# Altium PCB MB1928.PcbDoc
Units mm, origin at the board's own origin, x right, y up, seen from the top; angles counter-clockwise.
Board outline 32.1 x 44.98 mm, 4 copper layers (Top Layer, Layer 1, Layer 2, Bottom Layer), stack 0.76 mm thick; 39 components, 36 nets, 187 pads, 210 vias.
Unrouted connection lines stored in the file: 55.
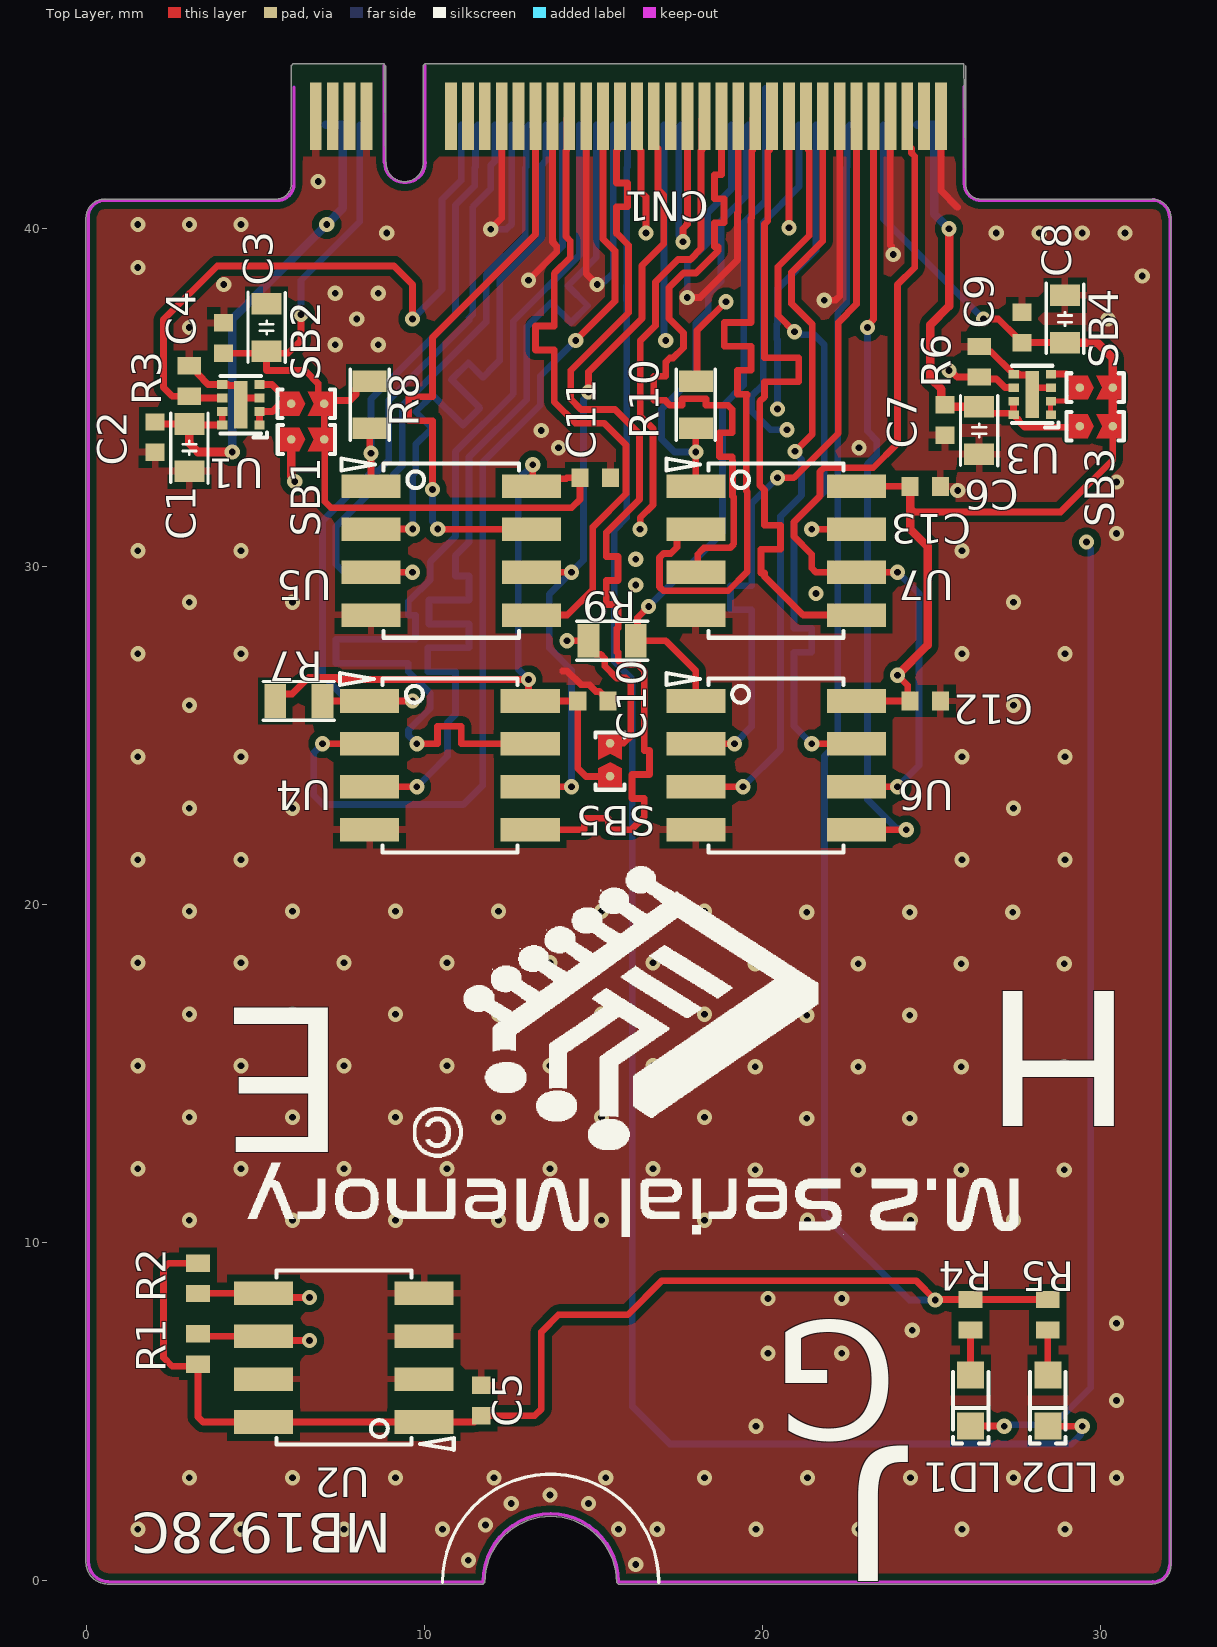
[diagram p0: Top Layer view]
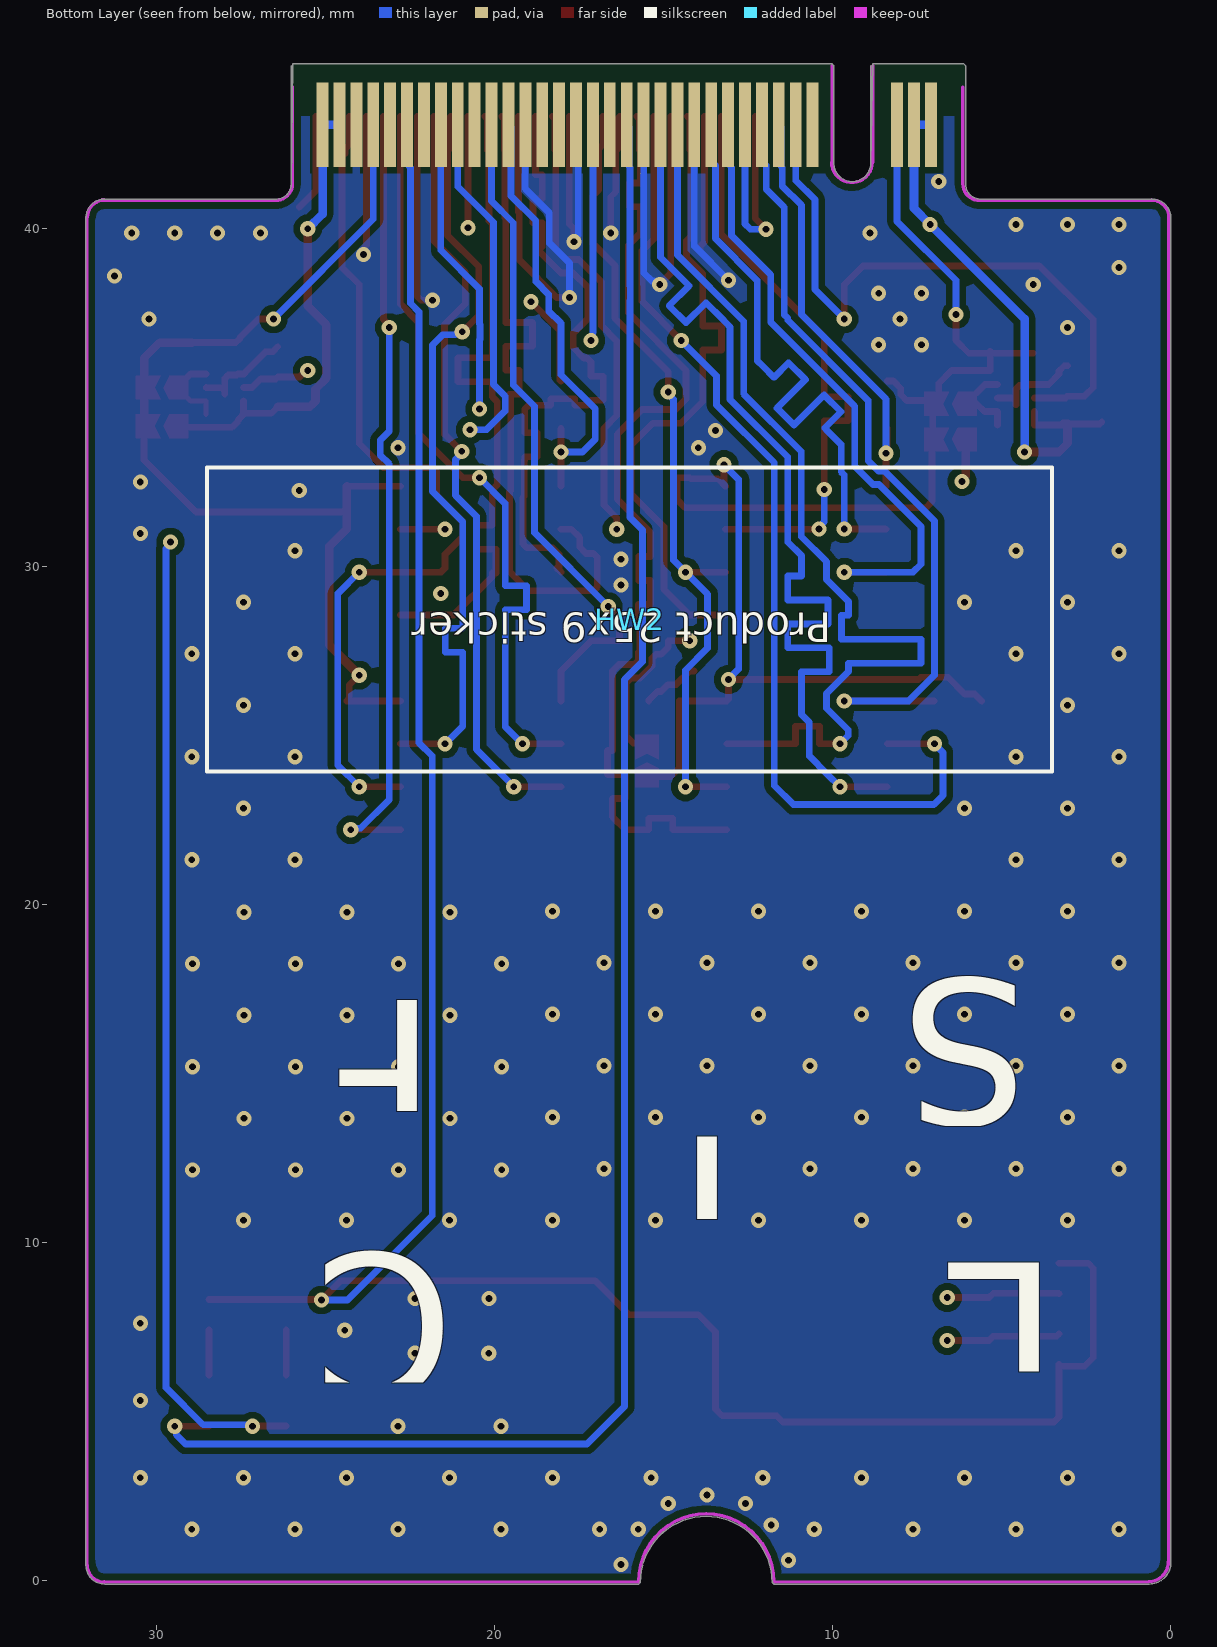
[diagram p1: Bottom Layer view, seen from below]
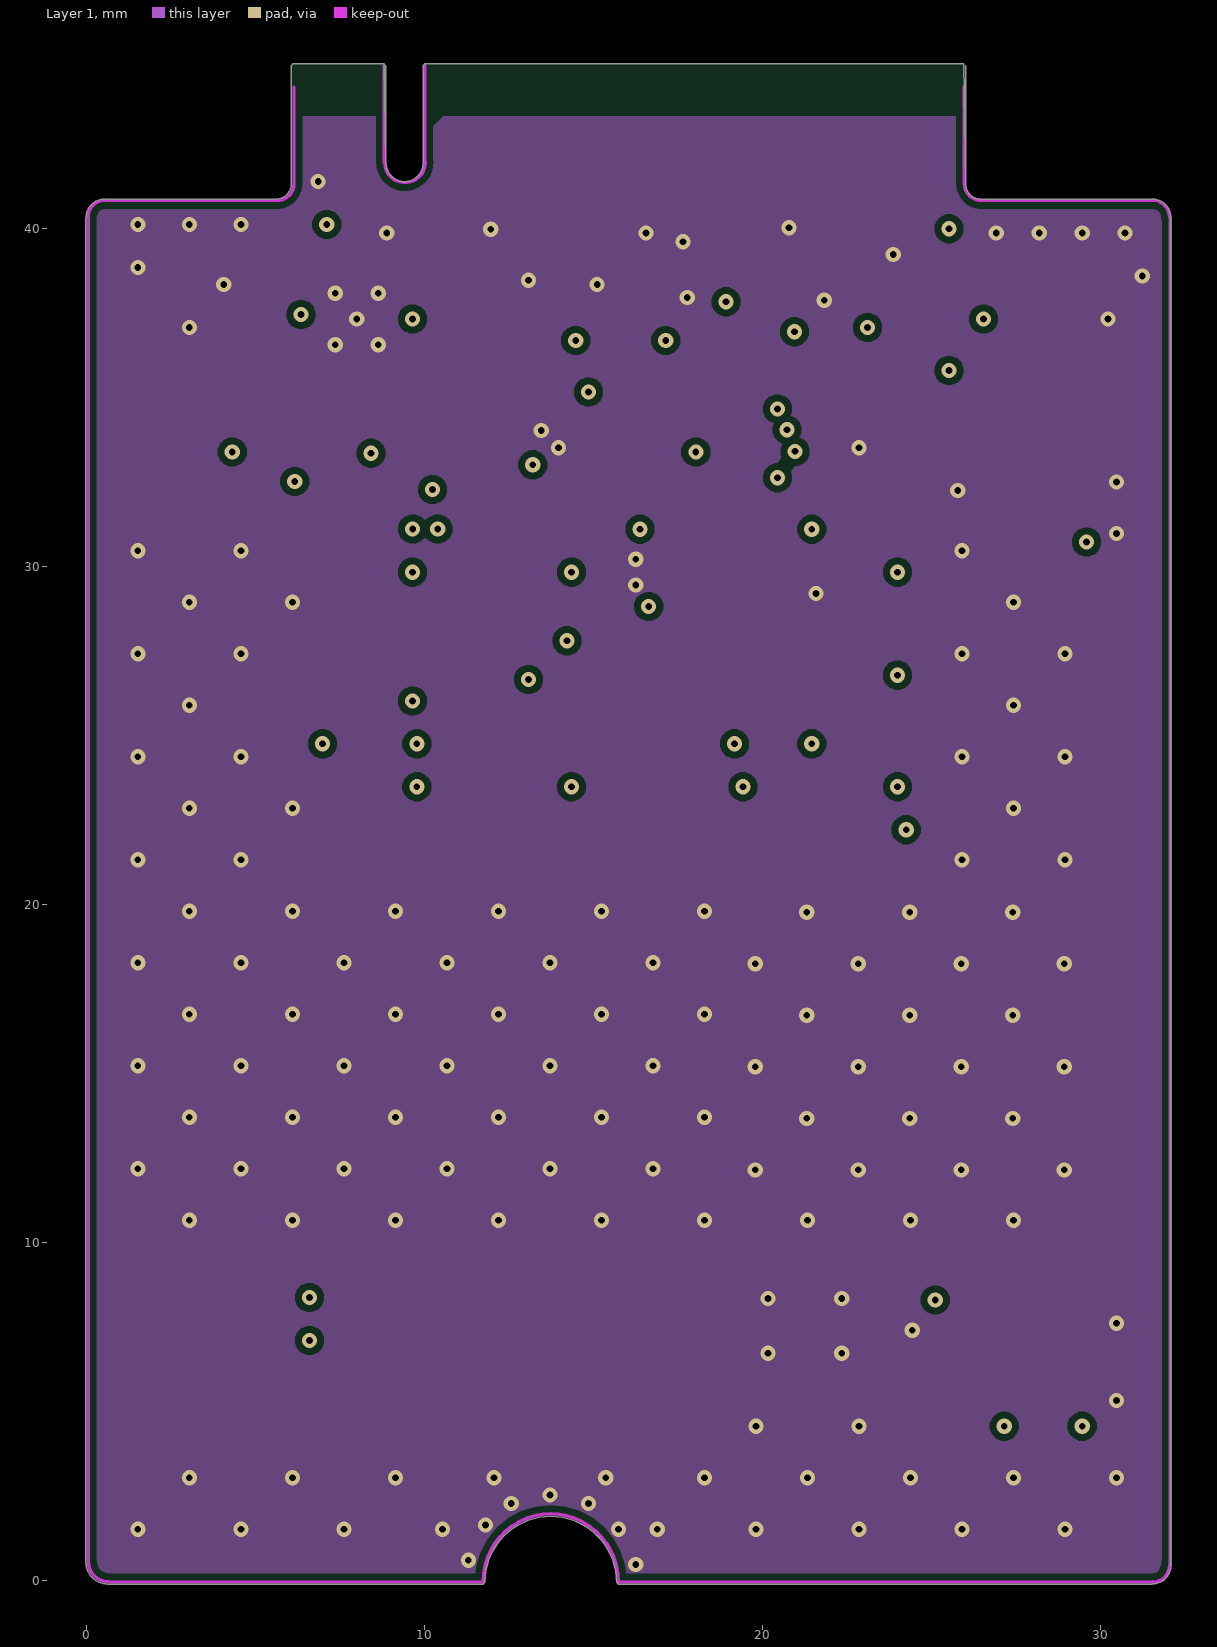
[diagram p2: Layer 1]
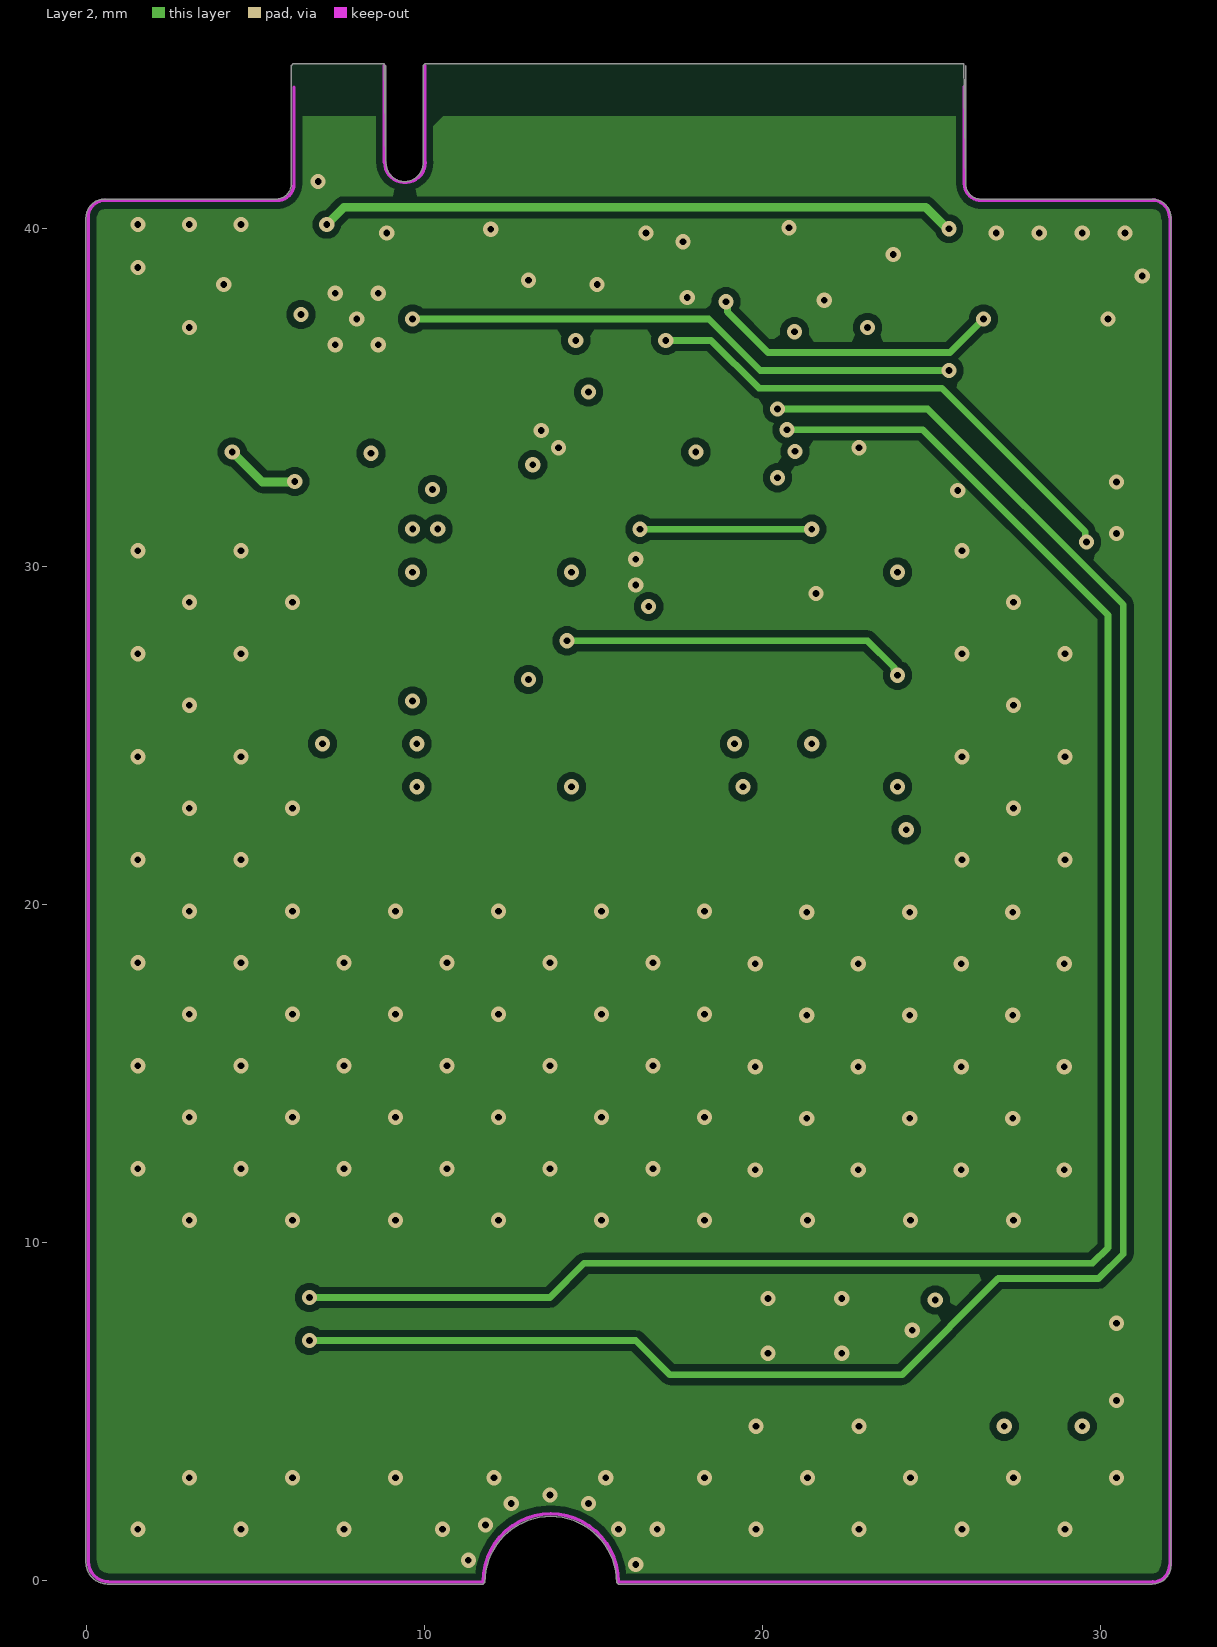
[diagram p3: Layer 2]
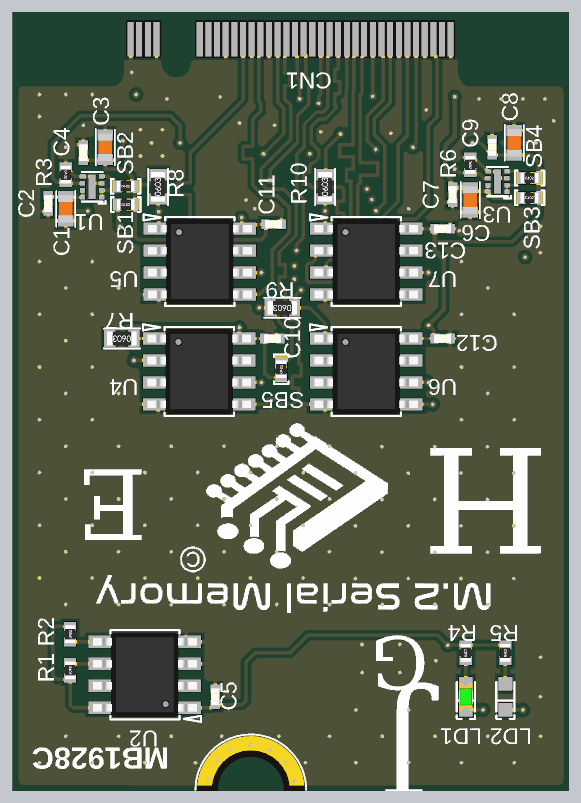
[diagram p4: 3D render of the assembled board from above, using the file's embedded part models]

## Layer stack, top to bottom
Top Solder: solder mask 0.018, Solder Resist, Dk 3.5
Top Layer: signal copper 0.036
Dielectric 2: prepreg 0.109, PP-006, Dk 4.1
Layer 1: signal copper 0.03
Dielectric 1: dielectric 0.41, FR-4, Dk 4.8
Layer 2: signal copper 0.03
Dielectric 3: prepreg 0.109, PP-006, Dk 4.1
Bottom Layer: signal copper 0.036
Bottom Solder: solder mask 0.018, Solder Resist, Dk 3.5

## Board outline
-0.011,0.543 ccw(c0.626,0.543) 0.626,-0.094 11.739,-0.094 11.789,-0.044 cw(c13.739,-0.044) 15.689,-0.044 15.739,-0.094 31.539,-0.094 31.54,-0.094 ccw(c31.539,0.456) 32.089,0.456 32.089,40.331 ccw(c31.539,40.331) 31.539,40.881 26.464,40.881 cw(c26.464,41.331) 26.015,41.331 26.015,44.831 26.015,41.331 25.964,44.881 10.014,44.881 9.964,44.831 9.964,41.951 cw(c9.414,41.951) 9.414,41.401 cw(c9.414,41.951) 8.864,41.951 8.864,44.831 8.864,41.951 8.814,44.881 6.114,44.881 6.064,44.831 6.064,41.331 cw(c5.614,41.331) 5.614,40.881 0.539,40.881 ccw(c0.539,40.331) -0.011,40.331

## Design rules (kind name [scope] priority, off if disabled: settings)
Clearance [All] p1: gap=0.2 ignorepadtopadclearanceinfootprint=TRUE except(0: Arc-Hole Track-Hole SMDPad-Hole THPad-Hole Via-Hole Fill-Hole Poly-Hole Region-Hole Text-Hole; 0.1: Arc-SMDPad Track-SMDPad)
ComponentClearance [All] p1: gap=0.2 collisioncheckmode=3 verticalgap=0.2 showdistances=FALSE
HoleSize [All] p1: absolutevalues=TRUE maxlimit=10 minlimit=0.025 maxpercent=80.000 minpercent=20.000
MatchedLengths MatchedLengths_3 [InNetClass('QSPI1')] p1: tolerance=1 checknetsindiffpair=FALSE checkdiffpairvsdiffpair=TRUE checkxsignals=TRUE checkothers=TRUE
MatchedLengths MatchedLengths_2 [InNetClass('QSPI2')] p2: tolerance=1 checknetsindiffpair=FALSE checkdiffpairvsdiffpair=TRUE checkxsignals=TRUE checkothers=TRUE
MatchedLengths MatchedLengths_1 [InNetClass('QSPI3')] p3: tolerance=1 checknetsindiffpair=FALSE checkdiffpairvsdiffpair=TRUE checkxsignals=TRUE checkothers=TRUE
MatchedLengths [InNetClass('QSPI4')] p4: tolerance=1 checknetsindiffpair=FALSE checkdiffpairvsdiffpair=TRUE checkxsignals=TRUE checkothers=TRUE
MinimumSolderMaskSliver [All] p1: minsoldermaskwidth=0.05
PlaneConnect [All] p1: planeconnectstyle=Relief reliefexpansion=0.508 reliefentries=4 reliefconductorwidth=0.21 reliefairgap=0.21
PolygonConnect PolygonConnect_via [IsVia] p1: connectstyle=Direct reliefconductorwidth=0.254 reliefentries=4 polygonreliefangle="90 Angle" airgapwidth=0.254
PolygonConnect [All] p2: connectstyle=Relief reliefconductorwidth=0.2 reliefentries=4 polygonreliefangle="90 Angle" airgapwidth=0.2
RoutingVias [All] p1: holewidth=0.3 width=0.8 viastyle="Through Hole" minholewidth=0.3 minwidth=0.8 maxholewidth=0.3 maxwidth=0.8
SilkToSilkClearance [All] p1: silktosilkclearance=0.1
SilkToSolderMaskClearance [IsPad] p1: minsilkscreentomaskgap=0.05 clearancetoexposedcopper=TRUE
SolderMaskExpansion [All] p1: expansion=0.102 istentingtop=FALSE
SupplyNets "Schematic Supply Nets_4" [InNet('VDDIO2')] p1: voltage=0.000
SupplyNets "Schematic Supply Nets_3" [InNet('GND')] p2: voltage=0.000
SupplyNets "Schematic Supply Nets_2" [InNet('VDDIO1')] p3: voltage=0.000
SupplyNets "Schematic Supply Nets_1" [InNet('3V3')] p4: voltage=0.000
SupplyNets "Schematic Supply Nets" [InNet('VDDI2C')] p5: voltage=0.000
Width [All] p1: maxlimit=1 minlimit=0.127 preferedwidth=0.254 toplayer_prefwidth=0.2 midlayer1_maxwidth=0.512 midlayer2_maxwidth=0.512 bottomlayer_prefwidth=0.2 minimp=50.000000 maximp=50.000000 favimp=50.000000
24 further rules are at their usual default settings.

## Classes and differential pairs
component class Project_Overview: HW1 HW2
net class QSPI4: QSPI4_D0 QSPI4_D1 QSPI4_D2 QSPI4_D3
net class QSPI3: QSPI3_D0 QSPI3_D1 QSPI3_D2 QSPI3_D3
net class QSPI2: QSPI2_D0 QSPI2_D1 QSPI2_D2 QSPI2_D3
net class QSPI1: QSPI1_D0 QSPI1_D1 QSPI1_D2 QSPI1_D3
component class U_Peripherals: C1 C2 C3 C4 C5 C6 C7 C8 C9 LD1 LD2 R1 R2 R3 R4 R5 R6 SB1 SB2 SB3 SB4 SB5 U1 U2 U3
component class U_M.2_Memory: C10 C11 C12 C13 CN1 R7 R8 R9 R10 U4 U5 U6 U7

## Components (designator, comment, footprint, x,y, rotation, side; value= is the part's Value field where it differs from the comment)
C1 "Capacitor" C0603 3.048,33.528 r90 top value=1uF
C2 "Capacitor" C0402 2.032,33.84 r90 top value=100nF
C3 "Capacitor" C0603 5.334,37.084 r270 top value=1uF
C4 "Capacitor" C0402 4.064,36.772 r270 top value=100nF
C5 "Capacitor" C0402 11.684,5.334 r270 top value=100nF
C6 "Capacitor" C0603 26.416,34.036 r90 top value=1uF
C7 "Capacitor" C0402 25.4,34.348 r90 top value=100nF
C8 "Capacitor" C0603 28.956,37.338 r270 top value=1uF
C9 "Capacitor" C0402 27.686,37.084 r270 top value=100nF
C10 "Capacitor" C0402 14.986,26.035 r180 top value=100nF
C11 "Capacitor" C0402 15.055,32.639 r180 top value=100nF
C12 "Capacitor" C0402 24.823,26.035 r180 top value=100nF
C13 "Capacitor" C0402 24.823,32.385 r180 top value=100nF
CN1 "M2-Generic_Module-KeyA" "M2_Key A" 6.114,44.831 r270 top locked value=M2
HW2 "STICKER_PRODUCT" STICKER_PRODUCT_25X9 16.002,28.448 r0 bottom value=N/A
LD1 "LED_green" LED_0603_OSRAM_LG-Q396-PS-35_GREEN_1A2K_H0P4 26.162,5.334 r270 top value=Green
LD2 "LED_red" LED_0603_VISHAY_VLMS1300-GS08_RED_1A2K_H0P8 28.448,5.334 r270 top value=Red
R1 "Resistor" R0402 3.302,6.858 r270 top value=10K
R2 "Resistor" R0402 3.302,8.948 r90 top value=10K
R3 "Resistor" R0402 3.048,35.502 r270 top value=10K
R4 "Resistor" R0402 26.162,7.874 r90 top value=220R
R5 "Resistor" R0402 28.448,7.874 r90 top value=220R
R6 "Resistor" R0402 26.416,36.068 r270 top value=10K
R7 "Resistor" R0603 6.288,26.035 r180 top value=100K
R8 "Resistor" R0603 8.382,34.798 r90 top value=100K
R9 "Resistor" R0603 15.559,27.813 r180 top value=100K
R10 "Resistor" R0603 18.034,34.798 r90 top value=100K
SB1 "SB_ON" SOLDER-BRIDGE_R0402-0R 6.513,33.773 r0 top value=0R
SB2 "SB_ON" SOLDER-BRIDGE_R0402-0R 6.51,34.829 r0 top value=0R
SB3 "SB_ON" SOLDER-BRIDGE_R0402-0R 29.845,34.163 r0 top value=0R
SB4 "SB_ON" SOLDER-BRIDGE_R0402-0R 29.845,35.306 r0 top value=0R
SB5 "SB_ON" SOLDER-BRIDGE_R0402-0R 15.494,24.257 r90 top value=0R
U1 "IC_LD56100DPUxxR" ICC_DFN8-EPAD_1P6X1P2_P040_H0P45 4.572,34.798 r90 top value=AP7368D-18RS4-7
U2 "M24128-DFMN6TP" ICC_SO8_5X4_P127 7.62,6.604 r90 top
U3 "IC_LD56100DPUxxR" ICC_DFN8-EPAD_1P6X1P2_P040_H0P45 27.991,35.103 r90 top value=AP7368D-18RS4-7
U4 "M95P32" ICC_SO8_5X4_P127 10.757,24.13 r270 top value=M95P32-IXMNT/E
U5 "M95P32" ICC_SO8_5X4_P127 10.795,30.48 r270 top value=M95P32-IXMNT/E
U6 "M95P32" ICC_SO8_5X4_P127 20.409,24.13 r270 top value=M95P32-IXMNT/E
U7 "M95P32" ICC_SO8_5X4_P127 20.409,30.48 r270 top value=M95P32-IXMNT/E

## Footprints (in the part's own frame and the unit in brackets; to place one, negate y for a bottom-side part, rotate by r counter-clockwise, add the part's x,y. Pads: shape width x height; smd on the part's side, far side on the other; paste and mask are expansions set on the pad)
C0402 [mm]
  rect 0.51x0.56 smd mask+0.05: 1(-0.45,0) 2(0.45,0)
  body extent -0.5,-0.3 0.5,0.3, height 0.4
C0603 [mm]
  rect 0.64x0.89 smd mask+0.05: 1(-0.7,0) 2(0.7,0)
  silkscreen extent -1.05,-0.55 1.02,0.55, body extent -0.9,-0.5 0.9,0.5, height 1.4
ICC_DFN8-EPAD_1P6X1P2_P040_H0P45 [mm] "MCD-02937"
  rect 0.26x0.3 smd mask+0.035: 1(-0.6,-0.55) 2(-0.2,-0.55) 3(0.2,-0.55) 4(0.6,-0.55) 5(0.6,0.55) 6(0.2,0.55) 7(-0.2,0.55) 8(-0.6,0.55)
  rect 1.4x0.4 smd mask+0.05: EP(0,0)
  silkscreen extent -0.97,-0.77 0.85,0.6, body extent -0.8,-0.65 0.8,0.65, height 0.51
ICC_SO8_5X4_P127 [mm]
  rect 0.7x1.75 smd mask+0.05: 1(-1.905,-2.375) 2(-0.635,-2.375) 3(0.635,-2.375) 4(1.905,-2.375) 5(1.905,2.375) 6(0.635,2.375) 7(-0.635,2.375) 8(-1.905,2.375)
  silkscreen extent -2.73,-3.25 2.58,2, body extent -2.57,-3 2.57,3, height 1.75
LED_0603_OSRAM_LG-Q396-PS-35_GREEN_1A2K_H0P4 [mm]
  rect 0.8x0.8 smd mask+0.05: 1(-0.75,0) 2(0.75,0)
  silkscreen extent -0.85,-0.53 1.28,0.53, body extent -0.85,-0.45 0.85,0.45, height 0.6
LED_0603_VISHAY_VLMS1300-GS08_RED_1A2K_H0P8 [mm]
  rect 0.8x0.8 smd mask+0.05: 1(-0.75,0) 2(0.75,0)
  silkscreen extent -0.85,-0.53 1.28,0.53, body extent -0.85,-0.45 0.85,0.45, height 0.8
"M2_Key A" [mm] "M2 PCB 0.8mm Key  A"
  rect 2x0.35 smd: 1(1.5,0.675) 3(1.5,1.175) 5(1.5,1.675) 7(1.5,2.175) 17(1.5,4.675) 19(1.5,5.175) 21(1.5,5.675) 23(1.5,6.175) 25(1.5,6.675) 27(1.5,7.175) 29(1.5,7.675) 31(1.5,8.175) 33(1.5,8.675) 35(1.5,9.175) 37(1.5,9.675) 39(1.5,10.175) 41(1.5,10.675) 43(1.5,11.175) 45(1.5,11.675) 47(1.5,12.175) 49(1.5,12.675) 51(1.5,13.175) 53(1.5,13.675) 55(1.5,14.175) 57(1.5,14.675) 59(1.5,15.175) 61(1.5,15.675) 63(1.5,16.175) 65(1.5,16.675) 67(1.5,17.175) 69(1.5,17.675) 71(1.5,18.175) 73(1.5,18.675) 75(1.5,19.175)
  rect 2.5x0.35 smd far side: 2(1.75,0.975) 4(1.75,1.475) 6(1.75,1.975) 16(1.75,4.475) 18(1.75,4.975) 20(1.75,5.475) 22(1.75,5.975) 24(1.75,6.475) 26(1.75,6.975) 28(1.75,7.475) 30(1.75,7.975) 32(1.75,8.475) 34(1.75,8.975) 36(1.75,9.475) 38(1.75,9.975) 40(1.75,10.475) 42(1.75,10.975) 44(1.75,11.475) 46(1.75,11.975) 48(1.75,12.475) 50(1.75,12.975) 52(1.75,13.475) 54(1.75,13.975) 56(1.75,14.475) 58(1.75,14.975) 60(1.75,15.475) 62(1.75,15.975) 64(1.75,16.475) 66(1.75,16.975) 68(1.75,17.475) 70(1.75,17.975) 72(1.75,18.475) 74(1.75,18.975)
R0402 [mm]
  rect 0.51x0.7 smd mask+0.05: 1(-0.45,0) 2(0.45,0)
  body extent -0.52,-0.3 0.52,0.3, height 0.4
R0603 [mm]
  rect 0.64x1 smd mask+0.05: 1(-0.7,0) 2(0.7,0)
  silkscreen extent -1.05,-0.58 1.05,0.58, body extent -0.9,-0.5 0.9,0.5, height 0.56
SOLDER-BRIDGE_R0402-0R [mil] "MCD-01619"
  round 10 smd paste-393.7: 1(-17.72,0) 2(20.67,0)
  Top Layer region: 1.48,13.78 8.37,0 1.48,-13.78 30.51,-13.78 30.51,13.78
  Top Layer region: -30.51,-13.78 -30.51,13.78 -8.37,13.78 -1.48,0 -8.37,-13.78
  silkscreen extent -33,-17 33,17, body extent -20,-12 20,12, height 14
STICKER_PRODUCT_25X9 [mm] "Sticker to mention board CPN code"
  silkscreen extent -12.5,-4.5 12.5,4.5

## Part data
C1 C3 C6 C8: library part MCD-01100, "Capacitor, MLCC, 1uF, 25V, X5R, +/-10%, 0603, T=0.8mm", Manufacturer=YAGEO, Manufacturer_Part_Number=CC0603KRX5R8BB105, Package=0603
C2 C4 C5 C7 C9 C10 C11 C12 C13: library part MCD-00006, "Capacitor, MLCC, 100nF, 16V, X7R, +/-10%, 0402, T=0.5mm", Manufacturer=YAGEO, Manufacturer_Part_Number=CC0402KRX7R7BB104, Package=0402
CN1: library part MCD-04116, "M2 Male connector, for Micromod, board edge connector 75-pin KEY A", Manufacturer=STMICROELECTRONICS, Manufacturer_Part_Number=N/A
HW2: library part MCD-00547, "Sticker product, 25x9mm", Manufacturer=N/A, Manufacturer_HQ_COO=Unknown
LD1: library part MCD-02901, "LED, Green, 2V, 20mA, 0603", Manufacturer=EVERLIGHT, Manufacturer_Part_Number=19-217/G7C-AN1P2/6T, Package=0603
LD2: library part MCD-02787, "LED, Red, 1V7 to 2V2, 5mA, 0603", Manufacturer=EVERLIGHT, Manufacturer_Part_Number=19-217/R6C-AL1M2VY/6T, Package=0603
R1 R2 R3 R6: library part MCD-00053, "Resistor, 10K, 0402, +/-1%, 1/16W", Manufacturer=YAGEO, Manufacturer_Part_Number=RC0402FR-0710KL, Package=0402
R4 R5: library part MCD-00427, "Resistor, 220R, 0402, +/-1%, 1/16W", Manufacturer=YAGEO, Manufacturer_Part_Number=RC0402FR-07220RL, Package=0402
R7 R8 R9 R10: library part MCD-00223, "Resistor, 100K, 0603, +/- 1%, 1/10W", Manufacturer=YAGEO, Manufacturer_Part_Number=RC0603FR-07100KL, Package=0603
SB1 SB2 SB3 SB4 SB5: library part MCD-01618, "Resistor, 0R, SB0402, 5%, 0.063W", Manufacturer=YAGEO, Manufacturer_Part_Number=RC0402JR-070RL, Package=0402
U1 U3: library part MCD-04735, "LDO, 1A, 1V8, Fast transient, low noise, 16uV RMS Noise, -40 To 85 degree C", Manufacturer="DIODES INCORPORATED", Manufacturer_Part_Number=AP7368D-18RS4-7, Package=DFN8
U2: library part MCD-00293, "Memory, EEPROM, 1V7 to 5V5, 128Kbit, 1MHz, SO-8", Manufacturer=STMICROELECTRONICS, Manufacturer_HQ_COO=EU, Package=SO-8
U4 U5 U6 U7: library part MCD-03804, "Memory, EEPROM, 1.6V to 3.6V, 32Mbit, 80MHz, SO8N, SPI interface", Manufacturer=STMICROELECTRONICS, Manufacturer_Part_Number=M95P32-IXMNT/E, Package=SO8N

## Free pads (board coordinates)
  round 0.508 on Mech16: 1(20.669,-22.395) 1(69.517,-22.395)

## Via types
v1: diameter 0.45, hole 0.2, Top Layer to Bottom Layer, tented both sides, 210 vias

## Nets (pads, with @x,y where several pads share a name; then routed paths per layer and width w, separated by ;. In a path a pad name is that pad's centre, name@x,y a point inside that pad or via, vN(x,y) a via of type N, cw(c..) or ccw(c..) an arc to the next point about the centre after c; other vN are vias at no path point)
3V3: C1.2 C2.2 C6.2 C7.2 CN1.2 CN1.4 CN1.72 CN1.74 SB1.1 SB3.1 U1.7 U1.8 U3.7 U3.8 | length 52
  Top Layer w0.2: C2.2 2.094,34.228 C1.2 ; C1.2@3.173,34.228 3.203,34.198 U1.8 U1.7 ; C6.2 26.608,34.544 U3.8@27.294,34.544 ; U3.7@27.432,34.906 27.432,34.506 27.452,34.506 27.482,34.476 27.482,34.456 27.582,34.356 27.582,34.323 27.774,34.131 29.348,34.131 29.38,34.163 SB3.1
  Top Layer w0.254: C1.2@3.173,34.228 C1.2 3.048,33.655 3.302,33.401 v1(4.318,33.401) ; SB1.1 6.063,32.682 6.166,32.58 v1(6.166,32.527) ; C7.2 25.298,34.9 25.298,35.262 24.975,35.585 24.975,37.167 25.527,37.719 v1(25.527,40.005) ; C7.2@25.462,34.736 C6.2
  Layer 2 w0.2: v1@25.474,40.005 v1(25.527,40.005)
  Layer 2 w0.254: v1(4.318,33.401) 5.207,32.512 v1@5.969,32.512 ; v1(7.112,40.132) 7.62,40.64 24.839,40.64 v1@25.474,40.005
  Bottom Layer w0.254: v1(4.318,33.401) 4.318,37.338 v1(7.112,40.132) 7.589,40.609 CN1.4 CN1.2 ; CN1.72 CN1.74 25.089,40.443 v1(25.527,40.005)
GND: C1.1 C2.1 C3.1 C4.1 C5.1 C6.1 C7.1 C8.1 C9.1 C10.1 C11.1 C12.1 C13.1 CN1.1 CN1.7 CN1.23 CN1.24 CN1.29 CN1.30 CN1.33 CN1.36 CN1.39 CN1.44 CN1.45 CN1.50 CN1.51 CN1.57 CN1.63 CN1.69 CN1.70 CN1.75 R3.1 R6.1 U1.3 U1.5 U1.EP U2.2 U2.3 U2.4 U2.7 U3.3 U3.5 U3.EP U4.4 U5.4 U6.4 U7.4 | length 74
  Top Layer w0.2: R3.1 3.143,35.952 3.298,35.797 3.298,35.702 3.602,35.398 U1.5 4.188,35.398 4.218,35.368 4.472,35.368 4.572,35.268 U1.EP@4.572,34.898 ; U1.EP U1.EP@4.572,34.898 ; U1.3 4.672,34.998 U1.EP@4.572,34.898 ; v1(11.967,39.994) 12.289,40.316 CN1.23 ; v1(13.081,38.481) 13.918,39.318 13.918,39.484 13.789,39.612 CN1.29 ; 14.097,26.924 14.224,26.924 14.633,26.515 14.874,26.515 15.074,26.315 15.181,26.315 15.436,26.06 C10.1 ; CN1.33 14.789,38.678 v1(15.113,38.354) ; CN1.39 16.364,43.256 16.364,42.364 16.414,42.314 16.414,41.099 16.561,40.952 v1(16.561,39.878) ; v1(17.653,39.624) 17.653,40.005 17.789,40.141 CN1.45 ; v1(17.78,37.973) 18.161,37.973 19.266,39.078 19.266,40.475 19.289,40.498 CN1.51 ; v1(20.789,40.036) CN1.57 ; v1(21.833,37.889) 21.837,37.892 22.172,37.892 22.289,38.01 CN1.63 ; CN1.69 23.789,39.517 23.828,39.478 23.828,39.291 v1(23.876,39.243) ; CN1.75 25.289,41.132 25.781,40.64 ; R6.1 26.571,36.363 26.775,36.363 27.382,35.756 27.382,35.736 27.412,35.706 27.432,35.706 27.598,35.706 27.628,35.676 27.882,35.676 27.982,35.576 U3.EP@27.982,35.205 ; U3.EP@27.982,35.106 U3.EP@27.982,35.205 ; U3.3@28.532,35.306 28.531,35.305 28.082,35.305 U3.EP@27.982,35.205
  Bottom Layer w0.2: v1(11.967,39.994) 12.435,39.994 12.589,40.148 CN1.24 ; v1(13.081,38.481) 14.089,39.489 CN1.30 ; v1(15.113,38.354) 15.181,38.354 15.288,38.462 15.348,38.462 15.589,38.703 CN1.36 ; CN1.44 17.526,43.018 17.526,39.819 17.653,39.692 v1(17.653,39.624) ; v1(17.78,37.973) 17.78,38.989 18.379,39.588 18.379,40.477 19.089,41.187 CN1.50
  other v1: 16.256,0.481 11.303,0.608 1.524,1.524 4.572,1.524 7.62,1.524 10.541,1.524 15.748,1.524 16.891,1.524 19.812,1.524 22.86,1.524 25.908,1.524 28.956,1.524 11.811,1.651 12.573,2.286 14.859,2.286 13.716,2.54 3.048,3.048 6.096,3.048 9.144,3.048 12.065,3.048 15.367,3.048 18.288,3.048 21.336,3.048 24.384,3.048 27.432,3.048 30.48,3.048 19.812,4.572 22.86,4.572 30.48,5.334 20.172,6.731 22.352,6.731 24.435,7.417 30.48,7.62 20.168,8.357 22.352,8.357 3.048,10.668 6.096,10.668 9.144,10.668 12.192,10.668 15.24,10.668 18.288,10.668 21.336,10.668 24.384,10.668 27.432,10.668 19.791,12.16 22.839,12.16 25.887,12.16 28.935,12.16 1.524,12.192 4.572,12.192 7.62,12.192 10.668,12.192 13.716,12.192 16.764,12.192 21.315,13.684 24.363,13.684 27.411,13.684 3.048,13.716 6.096,13.716 9.144,13.716 12.192,13.716 15.24,13.716 18.288,13.716 19.791,15.208 22.839,15.208 25.887,15.208 28.935,15.208 1.524,15.24 4.572,15.24 7.62,15.24 10.668,15.24 13.716,15.24 16.764,15.24 21.315,16.732 24.363,16.732 27.411,16.732 3.048,16.764 6.096,16.764 9.144,16.764 12.192,16.764 15.24,16.764 18.288,16.764 19.791,18.256 22.839,18.256 25.887,18.256 28.935,18.256 1.524,18.288 4.572,18.288 7.62,18.288 10.668,18.288 13.716,18.288 16.764,18.288 21.315,19.78 24.363,19.78 27.411,19.78 3.048,19.812 6.096,19.812 9.144,19.812 12.192,19.812 15.24,19.812 18.288,19.812 1.524,21.336 4.572,21.336 25.908,21.336 28.956,21.336 3.048,22.86 6.096,22.86 27.432,22.86 1.524,24.384 4.572,24.384 25.908,24.384 28.956,24.384 3.048,25.908 27.432,25.908 1.524,27.432 4.572,27.432 25.908,27.432 28.956,27.432 3.048,28.956 6.096,28.956 27.432,28.956 21.59,29.21 16.256,29.464 16.256,30.226 1.524,30.48 4.572,30.48 25.908,30.48 30.48,30.988 25.781,32.258 30.48,32.512 13.97,33.528 22.86,33.528 13.462,34.036 7.366,36.576 8.636,36.576 3.048,37.084 8.001,37.338 30.226,37.338 7.366,38.1 8.636,38.1 4.064,38.354 31.242,38.608 1.524,38.862 8.89,39.878 26.924,39.878 28.194,39.878 29.464,39.878 30.734,39.878 1.524,40.132 3.048,40.132 4.572,40.132 6.858,41.402
LDO_EN: CN1.18 R3.2 R6.2 U1.6 U3.6 | length 38.1
  Top Layer w0.2: U1.6 3.102,34.998 R3.2 2.54,35.052 2.286,35.306 2.286,37.318 3.874,38.906 9.1,38.906 9.652,38.354 v1(9.652,37.338) ; v1(25.527,35.814) 25.57,35.814 25.766,35.618 R6.2 26.474,35.56 26.924,35.56 27.178,35.306 U3.6@27.432,35.306
  Layer 2 w0.2: v1(9.652,37.338) 18.415,37.338 19.939,35.814 v1(25.527,35.814)
  Bottom Layer w0.2: v1(9.652,37.338) 10.522,38.208 10.522,40.868 11.089,41.435 CN1.18
LED1: CN1.42 LD1.2 | length 50.6
  Top Layer w0.2: LD1.2 27.148,4.584 v1(27.16,4.572)
  Layer 2 w0.2: v1(17.145,36.703) 18.484,36.703 19.898,35.289 25.31,35.289 29.557,31.042 29.557,30.768 v1(29.591,30.734)
  Bottom Layer w0.2: CN1.42 17.089,36.936 17.097,36.928 17.097,36.751 v1(17.145,36.703) ; v1(27.16,4.572) 27.208,4.619 28.622,4.619 29.718,5.715 29.718,30.539 29.591,30.666 v1(29.591,30.734)
LED2: CN1.38 LD2.2 | length 53.5
  Top Layer w0.2: LD2.2 28.46,4.572 v1(29.464,4.572)
  Bottom Layer w0.2: CN1.38 16.014,43.006 16.014,41.839 15.989,41.814 15.989,38.322 15.985,38.317 15.985,37.883 15.989,37.878 15.989,31.464 15.621,31.095 15.621,27.198 16.154,26.664 16.154,5.156 17.264,4.047 29.144,4.047 29.416,4.319 29.416,4.524 v1(29.464,4.572)
NetLD1_1: LD1.1 R4.1 | length 1.3
  Top Layer w0.2: LD1.1 R4.1
NetLD2_1: LD2.1 R5.1 | length 1.3
  Top Layer w0.2: LD2.1 R5.1
NetSB2_1: SB2.1 U1.1 U1.2 U1.4 | length 2.9
  Top Layer w0.2: U1.1 U1.2 5.504,34.598 5.735,34.829 SB2.1 5.49,35.398 U1.4 ; 5.883,34.619 5.883,34.925
NetSB4_1: SB4.1 U3.1 U3.2 U3.4 | length 2.5
  Top Layer w0.15: U3.1@28.532,34.506 28.532,34.906 28.995,34.906 SB4.1
  Top Layer w0.2: U3.4@28.532,35.706 28.995,35.706 SB4.1
QSPI1/2_CLK: CN1.41 U4.6 U5.6 | length 24
  Top Layer w0.2: U4.6 v1(14.351,23.495) ; U5.6 v1(14.351,29.845) ; v1(14.859,35.179) 14.859,35.771 16.438,37.35 16.438,38.917 17.086,39.565 17.086,40.993 16.914,41.164 16.914,42.381 16.789,42.506 CN1.41
  Bottom Layer w0.2: v1(14.351,23.495) 14.351,26.944 13.699,27.596 13.699,29.193 v1(14.351,29.845) 14.707,30.201 14.707,34.959 14.859,35.111 v1(14.859,35.179)
QSPI1_D0: CN1.37 U4.5 | length 31.1
  Top Layer w0.2: U4.5 14.63,22.225 14.731,22.225 14.731,22.565 15.439,22.565 15.439,22.225 16.129,22.225 16.51,22.606 16.51,23.049 16.51,23.149 16.144,23.149 16.144,23.857 16.662,23.857 16.662,24.565 16.51,24.565 16.51,25.527 16.51,26.289 16.51,26.924 16.321,27.113 15.856,27.113 15.739,27.23 15.739,27.375 15.739,27.475 15.697,27.475 15.697,28.183 15.739,28.183 15.739,28.891 15.386,28.891 15.386,29.599 15.731,29.599 15.731,30.307 15.386,30.307 15.386,31.02 16.364,31.998 16.364,33.928 15.638,34.654 14.642,34.654 14.332,34.964 14.332,35.815 16.038,37.521 16.038,39.519 15.711,39.846 15.689,39.867 15.689,39.946 15.689,40.654 16.014,40.654 16.014,41.362 15.689,41.362 15.689,42.037 15.689,42.314 15.714,42.339 15.714,43.256 CN1.37
QSPI1_D1: CN1.35 U4.2 | length 29.9
  Top Layer w0.2: v1(6.985,24.765) U4.2 ; v1(14.478,36.703) 15.638,37.863 15.638,39.353 15.289,39.702 CN1.35
  Bottom Layer w0.2: v1(6.985,24.765) 6.731,24.511 6.731,23.241 7.002,22.97 11.159,22.97 11.725,23.536 11.725,33.084 13.43,34.789 13.43,35.655 v1(14.478,36.703)
QSPI1_D2: CN1.34 U4.3 | length 29.7
  Top Layer w0.2: U4.3 v1(9.779,23.495)
  Bottom Layer w0.2: v1(9.779,23.495) 10.16,23.876 10.687,24.403 10.687,25.4 10.922,25.635 10.922,26.797 10.922,26.897 10.098,26.897 10.098,27.605 11.325,27.605 11.325,28.313 10.136,28.313 10.136,29.021 11.325,29.021 11.325,29.729 10.922,29.729 10.922,30.099 10.922,30.335 11.325,30.738 11.325,33.25 13.03,34.955 13.03,37.102 13.173,37.246 13.244,37.316 13.745,37.817 14.334,37.228 14.834,37.729 14.245,38.318 14.38,38.452 15.089,39.162 CN1.34
QSPI1_D3: CN1.32 U4.7 | length 30.2
  Top Layer w0.2: v1(9.779,24.765) 10.287,24.765 10.387,24.765 10.387,25.287 11.095,25.287 11.095,24.765 11.938,24.765 U4.7
  Bottom Layer w0.2: v1(9.779,24.765) 9.535,25.009 9.535,25.175 10.177,25.818 10.177,26.252 9.525,26.904 9.525,27.051 9.525,27.151 7.385,27.151 7.385,27.859 9.736,27.859 9.736,28.567 9.525,28.567 9.525,28.829 9.525,28.976 10.177,29.628 10.177,30.156 10.925,30.904 10.925,33.416 12.63,35.121 12.63,37.268 14.589,39.227 CN1.32
QSPI1_NCS: CN1.22 R7.1 U4.1 | length 24.1
  Top Layer w0.2: R7.1 U4.1 v1(9.652,26.035)
  Bottom Layer w0.2: v1(9.652,26.035) 7.747,26.035 6.985,26.797 6.985,31.362 8.461,32.838 8.637,32.838 8.945,33.146 8.945,34.922 11.322,37.299 11.322,37.357 11.43,37.465 11.43,40.645 11.964,41.179 11.964,41.814 11.964,41.881 12.089,42.006 CN1.22
QSPI2_D0: CN1.31 U5.5 | length 19.3
  Top Layer w0.2: U5.5 13.174,28.579 14.228,28.579 14.986,29.337 14.986,31.186 15.964,32.164 15.964,33.604 15.314,34.254 14.476,34.254 13.843,34.887 13.843,36.322 13.843,36.422 13.288,36.422 13.288,37.13 13.843,37.13 13.843,38.481 13.843,38.677 14.318,39.152 14.318,39.649 14.189,39.778 14.189,42.314 14.214,42.339 14.214,43.256 CN1.31
QSPI2_D1: CN1.28 U5.2 | length 18.6
  Top Layer w0.2: U5.2 8.431,31.126 v1(9.654,31.126)
  Bottom Layer w0.2: v1(9.654,31.126) 9.654,32.723 9.745,32.814 9.745,33.621 10.16,34.036 10.231,34.107 9.746,34.592 10.246,35.092 11.141,34.198 11.642,34.698 10.8,35.54 11.301,36.04 11.733,35.609 12.065,35.941 12.23,36.106 12.23,38.481 13.464,39.715 13.464,41.814 13.464,41.881 13.589,42.006 CN1.28
QSPI2_D2: CN1.26 U5.3 | length 19.1
  Top Layer w0.2: U5.3 v1(9.652,29.845)
  Bottom Layer w0.2: v1(9.652,29.845) 7.62,29.845 7.385,30.08 7.385,31.197 8.626,32.438 8.803,32.438 9.345,32.98 9.345,34.757 11.83,37.242 11.83,38.647 12.989,39.806 12.989,41.814 13.014,41.839 13.014,43.006 CN1.26
QSPI2_D3: CN1.27 U5.7 | length 17.7
  Top Layer w0.2: v1(10.243,32.294) 10.243,34.228 10.243,34.328 9.54,34.328 9.54,35.036 10.243,35.036 10.243,36.195 10.243,36.786 13.289,39.832 CN1.27 ; v1@10.406,31.115 U5.7
  Bottom Layer w0.2: v1(10.243,32.294) 10.243,31.346 10.4,31.189 v1(10.4,31.121)
QSPI2_NCS: CN1.20 R8.1 U5.1 | length 12.8
  Top Layer w0.2: R8.1 8.382,33.401 v1(8.42,33.363) U5.1
  Bottom Layer w0.2: v1(8.42,33.363) 8.42,34.963 10.922,37.465 10.922,40.702 11.489,41.269 11.489,41.814 11.514,41.839 11.514,43.006 CN1.20
QSPI3/4_CLK: CN1.71 U6.6 U7.6 | length 26.7
  Top Layer w0.2: U6.6 v1(24.003,23.495) ; v1(24.003,29.845) U7.6 21.58,29.845 21.463,29.962 21.463,30.373 20.938,30.898 20.938,31.332 21.709,32.103 21.709,32.818 21.826,32.935 23.283,32.935 24.003,33.655 24.003,38.354 24.511,38.862 24.511,42.151 24.414,42.248 24.414,42.381 24.289,42.506 CN1.71
  Bottom Layer w0.2: v1(24.003,23.495) 24.638,24.13 24.638,29.21 v1(24.003,29.845)
QSPI3_D0: CN1.67 U6.5 | length 23.5
  Top Layer w0.2: U6.5 v1(24.257,22.225) ; v1(23.114,37.084) 23.114,37.151 23.289,37.326 CN1.67
  Bottom Layer w0.2: v1(23.114,37.084) 23.114,34.016 23.385,33.745 23.385,33.311 23.114,33.04 23.114,23.114 23.959,22.269 24.213,22.269 v1(24.257,22.225)
QSPI3_D1: CN1.65 U6.2 | length 22.7
  Top Layer w0.2: U6.2 v1(19.177,24.765) ; v1(20.447,32.639) 20.934,32.639 22.25,33.955 22.25,37.236 22.789,37.775 CN1.65
  Bottom Layer w0.2: v1(19.177,24.765) 19.685,25.273 19.685,28.636 19.685,28.736 19.059,28.736 19.059,29.444 19.685,29.444 19.685,30.607 19.685,31.877 v1(20.447,32.639)
QSPI3_D2: CN1.61 U6.3 | length 22.9
  Top Layer w0.2: U6.3 v1(19.431,23.495) ; v1(20.971,33.419) 21.48,33.928 21.48,37.174 20.866,37.788 20.866,38.715 21.789,39.639 CN1.61
  Bottom Layer w0.2: v1(19.431,23.495) 20.538,24.602 20.538,31.498 21.158,32.118 21.158,33.177 20.971,33.364 v1(20.971,33.419)
QSPI3_D3: CN1.59 U6.7 | length 22.8
  Top Layer w0.2: v1(20.955,36.957) 20.466,37.446 20.466,38.881 21.389,39.804 21.389,42.314 21.364,42.339 21.364,43.256 CN1.59 ; v1(21.463,24.765) U6.7
  Bottom Layer w0.2: v1(20.955,36.957) 21.003,36.909 21.13,36.909 21.167,36.872 21.528,36.872 21.836,36.565 21.836,32.23 20.938,31.332 20.938,30.988 20.938,28.186 21.46,28.186 21.46,27.478 20.938,27.478 20.938,26.67 20.938,25.29 v1(21.463,24.765)
QSPI3_NCS: CN1.54 R9.1 U6.1 | length 21
  Top Layer w0.2: v1(16.637,28.829) 16.304,28.496 16.304,27.858 R9.1 17.145,27.813 18.034,26.924 U6.1
  Bottom Layer w0.2: v1(16.637,28.829) 18.821,31.013 18.821,34.754 19.448,35.381 19.448,40.182 20.089,40.824 CN1.54 CN1.54@20.089,44.156
QSPI4_D0: CN1.55 U7.5 | length 20.2
  Top Layer w0.2: CN1.55 20.214,43.256 20.214,42.339 20.164,42.289 20.164,40.242 20.066,40.144 20.066,36.703 20.066,36.187 21.08,36.187 21.08,35.479 20.066,35.479 20.066,35.032 19.922,34.888 19.922,34.671 19.922,32.422 20.066,32.278 20.066,31.623 20.066,31.234 20.538,31.234 20.538,30.526 19.958,30.526 19.958,29.818 20.066,29.818 20.066,29.718 21.209,28.575 U7.5
QSPI4_D1: CN1.53 U7.2 | length 21.2
  Top Layer w0.2: U7.2 17.728,31.115 17.478,30.865 17.478,30.582 17.291,30.395 17.076,30.395 16.959,30.278 16.959,29.412 17.076,29.295 18.992,29.295 19.558,29.861 19.558,32.22 19.522,32.256 19.522,34.478 19.522,35.054 19.558,35.09 19.558,35.11 19.268,35.11 19.268,35.818 19.666,35.818 19.666,36.526 18.877,36.526 18.877,37.234 19.666,37.234 19.666,38.042 19.666,40.309 19.689,40.333 19.689,42.314 19.714,42.339 19.714,43.256 CN1.53
QSPI4_D2: CN1.49 U7.3 | length 20.3
  Top Layer w0.2: 18.091,30.378 18.091,29.902 U7.3 U7.3@18.161,29.972 ; 18.161,30.448 18.278,30.565 19.041,30.565 19.158,30.682 19.158,32.054 19.122,32.09 19.122,33.147 19.109,33.16 19.109,33.26 18.734,33.26 18.734,33.968 19.109,33.968 19.109,34.417 19.109,34.665 18.992,34.782 18.956,34.782 18.334,34.782 18.334,34.978 17.626,34.978 17.626,34.782 17.526,34.782 17.262,34.782 17.211,34.833 17.145,34.899 17.145,34.933 16.786,34.933 16.786,35.641 17.145,35.641 17.145,35.961 17.145,36.061 17.262,36.178 17.362,36.178 17.67,36.486 17.67,36.92 17.238,37.352 17.238,38.262 17.675,38.699 18.036,38.699 18.689,39.352 18.689,39.376 18.689,39.476 18.589,39.476 18.589,40.184 18.866,40.184 18.866,40.892 18.589,40.892 18.589,41.6 18.789,41.6 18.789,41.947 CN1.49
QSPI4_D3: CN1.47 U7.7 | length 19.9
  Top Layer w0.2: v1@16.386,31.121 16.386,31.455 16.764,31.833 16.764,34.094 16.386,34.472 16.386,36.686 16.838,37.138 16.838,38.428 17.509,39.099 17.87,39.099 18.189,39.418 18.189,42.314 18.214,42.339 18.214,43.256 CN1.47 ; v1(21.463,31.115) U7.7
  Layer 2 w0.2: v1(16.383,31.115) v1(21.463,31.115)
QSPI4_NCS: CN1.52 R10.1 U7.1 | length 13.3
  Top Layer w0.2: U7.1 R10.1
  Bottom Layer w0.2: v1(18.034,33.401) 17.399,33.401 17.018,33.782 17.018,34.671 18.034,35.687 18.034,37.211 18.398,37.575 18.398,38.063 18.779,38.444 18.779,39.657 18.779,40.242 19.514,40.977 19.514,43.006 CN1.52
SCL: CN1.60 R1.1 U2.6 | length 70.1
  Top Layer w0.2: R1.1 3.371,7.239 U2.6 5.372,7.112 v1(6.604,7.112)
  Layer 2 w0.2: v1(6.604,7.112) 16.256,7.112 17.272,6.096 24.13,6.096 26.978,8.944 29.95,8.944 30.68,9.674 30.68,28.883 24.892,34.671 v1(20.447,34.671)
  Bottom Layer w0.2: v1(20.447,34.671) 20.447,36.723 20.43,36.74 20.43,37.174 20.447,37.191 20.447,38.227 21.589,39.369 CN1.60
SDA: CN1.58 R2.1 U2.5 | length 68.4
  Top Layer w0.2: R2.1 3.313,8.509 U2.5 5.372,8.382 v1(6.604,8.382)
  Layer 2 w0.2: v1(6.604,8.382) 13.716,8.382 14.732,9.398 20.066,9.398 20.269,9.398 29.771,9.398 30.226,9.853 30.226,28.575 24.74,34.061 v1(20.729,34.061)
  Bottom Layer w0.2: v1(20.729,34.061) 20.236,34.061 19.685,34.612 19.685,35.052 20.03,35.397 20.03,40.199 21.089,41.258 CN1.58
VDDI2C: C5.2 CN1.64 R1.2 R2.2 R4.2 R5.2 U2.1 U2.8 | length 71.8
  Top Layer w0.2: R2.2 2.435,9.398 2.286,9.249 2.286,6.604 2.54,6.35 3.244,6.35 R1.2 3.302,4.848 3.451,4.699 U2.8 U2.1 11.474,4.699 11.659,4.884 C5.2 13.266,4.884 13.462,5.08 13.462,5.588 13.462,7.366 13.97,7.874 16.022,7.874 17.029,8.882 24.544,8.882 v1(25.118,8.308) 25.134,8.324 R4.2 R5.2
  Bottom Layer w0.2: CN1.64 22.514,43.006 22.514,41.839 22.489,41.814 22.489,37.802 22.236,37.548 22.236,24.795 21.844,24.404 21.844,10.813 24.349,8.308 v1(25.118,8.308)
VDDIO1: C3.2 C4.2 C10.2 C11.2 CN1.6 R7.2 R8.2 SB1.2 SB2.2 SB5.1 U4.8 U5.8 | length 47.5
  Top Layer w0.2: C4.2 5.272,36.322 C3.2 ; R7.2 5.794,26.241 6.091,26.241 6.585,26.735 7.391,26.735 7.456,26.67 v1(13.081,26.67) 13.081,26.086 U4.8 C10.2 14.536,24.052 14.786,23.803 15.49,23.803 SB5.1 ; v1(6.35,37.465) 6.35,36.703 5.969,36.322 5.396,36.322 C3.2 ; 6.858,34.925 SB2.2@7.035,34.925 ; 7.035,33.577 7.055,33.557 ; R8.2 8.202,35.498 7.982,35.278 7.982,35.098 7.809,34.925 7.146,34.925 7.05,34.829 SB2.2 ; v1(13.208,33.02) 13.208,32.423 U5.8 13.395,32.61 14.195,32.61 14.224,32.639 C11.2 14.605,31.994 14.361,31.75 7.239,31.75 7.055,31.934 7.055,33.718 7.048,33.724 7.048,33.762 SB1.2 7.038,34.826 SB2.2 ; C3.2 5.334,35.814 6.477,35.814 6.858,35.433 6.858,35.005 SB2.2
  Bottom Layer w0.2: v1(6.35,37.465) 6.35,38.481 8.089,40.22 CN1.6 ; v1(13.081,26.67) 12.776,26.975 12.776,32.588 v1(13.208,33.02)
VDDIO2: C8.2 C9.2 C12.2 C13.2 CN1.68 R9.2 R10.2 SB3.2 SB4.2 SB5.2 U6.8 U7.8 | length 58
  Top Layer w0.2: v1(14.224,27.813) R9.2 14.859,27.633 15.079,27.413 15.222,27.413 15.339,27.296 15.339,27.064 15.69,26.713 15.959,26.713 16.11,26.562 16.11,25 15.892,24.782 SB5.2 ; R10.2 18.07,35.534 18.07,36.993 v1(18.923,37.846) ; U6.8 C12.2 24.302,26.106 24.302,26.498 v1(24.003,26.797) ; U7.8 C13.2 ; 24.373,31.755 24.506,31.623 28.829,31.623 30.37,33.164 SB3.2 ; v1(26.543,37.338) 26.982,37.338 27.533,36.787 27.533,36.762 27.661,36.634 C9.2 27.69,36.638 C8.2
  Top Layer w0.254: v1(24.003,26.797) 24.892,27.686 24.892,30.607 24.373,31.126 24.373,31.755 C13.2 ; C8.2 29.91,36.638 30.37,36.178 SB4.2 SB3.2
  Layer 2 w0.2: v1(14.224,27.813) 23.114,27.813 23.895,27.032 23.895,26.972 24.003,26.865 v1(24.003,26.797) ; v1(18.923,37.846) 18.967,37.802 18.967,37.548 20.168,36.347 25.552,36.347 v1(26.543,37.338)
  Bottom Layer w0.2: CN1.68 23.589,40.292 v1(26.543,37.338)
pads on no net: CN1.3 CN1.5 CN1.16 CN1.17 CN1.19 CN1.21 CN1.25 CN1.40 CN1.43 CN1.46 CN1.48 CN1.56 CN1.62 CN1.66 CN1.73

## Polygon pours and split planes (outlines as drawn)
GND on Layer 1 "GND_L02_P001" (solid, pour order 1): 0,0 11.43,0 11.526,0.096 11.789,0.994 11.938,1.143 13.081,2.032 14.478,2.032 15.739,0.543 16.002,0 31.75,0 32.131,0.381 32.131,40.894 26.035,40.894 26.035,43.331 10.565,43.331 9.906,42.672 9.906,41.656 9.652,41.402 9.144,41.402 8.763,41.783 8.763,43.331 6.096,43.331 6.096,41.148 5.715,40.767 0.635,40.767 0.508,40.894 0,40.894
GND on Layer 2 "GND_L03_P002" (solid, pour order 2): 0,0 11.43,0 11.684,0.254 11.789,0.994 11.938,1.143 13.081,2.032 14.351,2.032 15.739,0.644 16.002,0 31.75,0 32.131,0.381 32.131,40.894 26.035,40.894 26.035,43.331 10.565,43.331 9.906,42.672 9.906,41.656 9.652,41.402 9.144,41.402 8.763,41.783 8.763,43.331 6.096,43.331 6.096,41.148 5.715,40.767 0.635,40.767 0.508,40.894 0,40.894
GND on Bottom Layer "GND_L04_P003" (solid, pour order 3): 0,0 11.43,0 11.537,0.107 11.789,1.013 11.938,1.143 12.954,1.905 14.605,1.905 15.82,0.779 16.002,0 31.75,0 32.131,0.381 32.131,40.894 26.035,40.894 26.035,43.331 10.565,43.331 9.906,42.672 9.906,41.656 9.652,41.402 9.144,41.402 8.763,41.783 8.763,43.331 6.096,43.331 6.096,41.148 5.715,40.767 0.635,40.767 0.508,40.894 0,40.894
GND on Top Layer "GND_L01_P000" (solid, pour order 0): 0,0 11.43,0 11.789,0.359 11.789,0.994 11.938,1.143 13.081,1.905 14.63,1.905 15.739,0.889 15.833,0 31.75,0 32.131,0.381 32.131,40.894 26.035,40.894 26.035,43.331 10.565,43.331 9.906,42.672 9.906,41.656 9.652,41.402 9.144,41.402 8.763,41.783 8.763,43.331 6.096,43.331 6.096,41.148 5.715,40.767 0.635,40.767 0.508,40.894 0,40.894

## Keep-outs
Keep-Out Layer:
  lines w0.1: 0.051,0.562 0.051,40.349 cw(c0.551,40.349) 0.551,40.849 ; 0.064,0.562 ccw(c0.651,0.562) 0.651,-0.025 11.739,-0.044 ; 0.551,40.84 5.644,40.84 ccw(c5.644,41.34) 6.144,41.34 6.144,44.2 ; 8.814,41.971 8.814,44.831 ; 8.827,41.971 ccw(c9.427,41.971) 10.027,41.971 ; 10.014,41.971 10.014,44.831 ; 11.739,-0.019 cw(c13.739,-0.019) 15.739,-0.019 ; 15.739,-0.044 31.549,-0.025 ; 25.978,44.203 25.978,41.343 ccw(c26.478,41.343) 26.478,40.843 31.571,40.843 ; 31.547,40.85 cw(c31.547,40.35) 32.047,40.35 ; 31.549,-0.039 ccw(c31.549,0.461) 32.049,0.461 ; 32.068,0.461 32.068,40.35

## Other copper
Top Layer:
  text ".Layer_Name" at 9,-16.047 h3
  text ".GTL" at 50.695,-16.047 h3
Layer 1:
  text ".Layer_Name" at 9,-16.047 h3
  text ".G1" at 50.695,-16.047 h3
Layer 2:
  text ".Layer_Name" at 8.925,-16.047 h3
  text ".G2" at 50.62,-16.047 h3
Bottom Layer:
  text ".GBL" at 39.491,-16.079 h3
  text ".Layer_Name" at 80.805,-16.079 h3

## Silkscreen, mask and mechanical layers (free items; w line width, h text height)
Top Overlay:
  drawing of 32 lines, arcs and shapes, not listed
  text "H" at 30.988,19.718 h12 r180
  text "E" at 7.74,18.47 h8 r180
  text "G" at 24.003,8.819 h6 r180
  text "J" at 24.003,4.703 h10 r180
  text "MB1928C" at 9.017,2.389 h2 r180
  text ".Layer_Name" at 9,-16.047 h3
  text ".GTO" at 50.695,-16.047 h3
Bottom Overlay:
  text "F" at 21.717,19.453 h12 r180
  text "S" at 4.191,19.304 h8 r180
  text "I" at 12.827,15.42 h12 r180
  text "C" at 21.198,11.96 h12 r180
  text "L" at 3.302,11.691 h12 r180
  text ".GBO" at 39.491,-16.079 h3
  text ".Layer_Name" at 80.805,-16.079 h3
Top Paste:
  text ".Layer_Name" at 8.973,-16.037 h3
  text ".GTP" at 50.667,-16.037 h3
Bottom Paste:
  text ".GBP" at 39.382,-16.064 h3
  text ".Layer_Name" at 80.696,-16.064 h3
Top Solder:
  lines w1.2: 11.239,-0.044 cw(c13.739,-0.044) 16.239,-0.044
  text ".Layer_Name" at 8.998,-16.112 h3
  text ".GTS" at 50.692,-16.112 h3
Bottom Solder:
  lines w1.2: 11.239,-0.044 cw(c13.739,-0.044) 16.239,-0.044
  text ".GBS" at 39.407,-16.139 h3
  text ".Layer_Name" at 80.721,-16.139 h3
M1-Board Shape:
  lines w0.1: 11.014,44.831 25.964,44.831 ; 31.514,40.831 26.464,40.831 ; 31.539,40.831 cw(c31.539,40.331) 32.039,40.331 ; 32.039,40.306 32.039,0.456 cw(c31.539,0.456) 31.539,-0.044 15.739,-0.044 ccw(c13.739,-0.044) 11.739,-0.044 0.626,-0.044 cw(c0.626,0.543) 0.039,0.543 0.039,40.331 cw(c0.539,40.331) 0.539,40.831 5.614,40.831 ; 5.614,40.831 ccw(c5.614,41.331) 6.114,41.331 ; 5.614,40.831 ccw(c5.614,41.331) 6.114,41.331 ; 5.614,40.831 ccw(c5.614,41.331) 6.114,41.331 ; 6.114,41.331 6.114,44.831 ; 6.114,41.331 6.114,44.831 ; 6.114,41.331 6.114,44.831 ; 6.114,44.831 8.814,44.831 ; 6.114,44.831 8.814,44.831 ; 8.814,41.951 ccw(c9.414,41.951) 10.014,41.951 ; 8.814,41.951 ccw(c9.414,41.951) 10.014,41.951 ; 8.814,41.951 8.814,44.831 ; 8.814,41.951 8.814,44.831 ; 10.014,41.951 10.014,44.831 ; 10.014,41.951 10.014,44.831 ; 10.014,44.831 25.964,44.831 ; 10.014,44.831 25.964,44.831 ; 25.964,41.331 ccw(c26.464,41.331) 26.464,40.831 ; 25.964,41.331 ccw(c26.464,41.331) 26.464,40.831 ; 25.964,41.331 ccw(c26.464,41.331) 26.464,40.831 ; 25.964,41.331 25.964,44.831 ; 25.964,41.331 25.964,44.831 ; 25.964,41.331 25.964,44.831
M2-Board Dimensions:
  text ".Layer_Name" at 9,-16.047 h3
  text ".GM2" at 50.695,-16.047 h3
M14-Top Assembly:
  text ".Layer_Name" at 9,-16.047 h3
  text ".GM14" at 50.695,-16.047 h3
M15-Bottom Assembly:
  text ".GM15" at 39.491,-16.079 h3
  text ".Layer_Name" at 80.805,-16.079 h3
Drill Drawing:
  drawing of 432 lines, arcs and shapes, not listed
  text "Layer" at 1.968,146.83 h1.52
  text "Name" at 12.38,146.83 h1.52
  text "Material" at 35.996,146.83 h1.52
  text "Thickness" at 57.834,146.83 h1.52
  text "Constant" at 74.34,146.83 h1.52
  text "Board Layer Stack" at 88.814,146.83 h1.52
  text "Top Overlay" at 12.38,143.782 h1.52
  text "Top Solder" at 12.38,140.734 h1.52
  text "Solder Resist" at 35.996,140.734 h1.52
  text "0.018mm" at 57.834,140.734 h1.52
  text "3.5" at 74.34,140.734 h1.52
  text "1" at 1.968,137.686 h1.52
  text "Top Layer" at 12.38,137.686 h1.52
  text "0.036mm" at 57.834,137.686 h1.52
  text "Dielectric 2" at 12.38,134.638 h1.52
  text "PP-006" at 35.996,134.638 h1.52
  text "0.109mm" at 57.834,134.638 h1.52
  text "4.1" at 74.34,134.638 h1.52
  text "2" at 1.968,131.59 h1.52
  text "Layer 1" at 12.38,131.59 h1.52
  text "CF-004" at 35.996,131.59 h1.52
  text "0.030mm" at 57.834,131.59 h1.52
  text "Dielectric 1" at 12.38,128.542 h1.52
  text "FR-4" at 35.996,128.542 h1.52
  text "0.410mm" at 57.834,128.542 h1.52
  text "4.8" at 74.34,128.542 h1.52
  text "3" at 1.968,125.494 h1.52
  text "Layer 2" at 12.38,125.494 h1.52
  text "CF-004" at 35.996,125.494 h1.52
  text "0.030mm" at 57.834,125.494 h1.52
  text "Dielectric 3" at 12.38,122.446 h1.52
  text "PP-006" at 35.996,122.446 h1.52
  text "0.109mm" at 57.834,122.446 h1.52
  text "4.1" at 74.34,122.446 h1.52
  text "4" at 1.968,119.398 h1.52
  text "Bottom Layer" at 12.38,119.398 h1.52
  text "0.036mm" at 57.834,119.398 h1.52
  text "Bottom Solder" at 12.38,116.35 h1.52
  text "Solder Resist" at 35.996,116.35 h1.52
  text "0.018mm" at 57.834,116.35 h1.52
  text "3.5" at 74.34,116.35 h1.52
  text "Bottom Overlay" at 12.38,113.302 h1.52
  text "Total board thickness:" at 1.968,110.254 h1.52
  text "0.796mm" at 57.834,110.254 h1.52
  text "THE COMPONENTS WITH PLATED THROUGH HOLE (PTH) MAY BE WELDED (CABLED) IN \"PIN-IN-PASTE\" MODE (IF NECESSARY)" at 0.091,104.374 h3.5
  text "PCB SPECIFICATIONS :" at 1.127,97.203 h3
  text "PCB : TYPE 3" at 149.539,96.971 h3
  text "A.   MATERIAL :" at 1.127,93.203 h3
  text "FR-4" at 39.627,93.203 h3
  text "TG-170" at 56.127,93.203 h3
  text "X  TG-150" at 74.377,93.203 h3
  text "TG-140" at 90.377,93.203 h3
  text "ASPECT-RATIO, AXE Z :" at 149.539,91.471 h3
  text "B.   MATERIAL FAMILY :" at 1.127,90.203 h3
  text "N/A" at 39.627,90.203 h3
  text "C.   SOLDERMASK COLOR :" at 1.127,87.203 h3
  text "GREEN" at 39.627,87.203 h3
  text "WHITE" at 56.127,87.203 h3
  text "RED" at 74.377,87.203 h3
  text "X  BLUE" at 90.377,87.203 h3
  text "6:1 to 8:1 / LEVEL \"B\"" at 149.557,84.723 h3
  text "D.   SILKSCREEN COLOR :" at 1.127,84.203 h3
  text "X  WHITE" at 39.627,84.203 h3
  text "YELLOW" at 56.127,84.203 h3
  text "BLACK" at 74.377,84.203 h3
  text "Blue ink PANTONE 2955" at 90.377,84.203 h3
  text "E.   SURFACE FINISH :" at 1.127,81.203 h3
  text "X  ENIG" at 39.627,81.203 h3
  text "IMMERSION SILVER" at 56.127,81.203 h3
  text "IMMERSION TIN" at 90.377,81.203 h3
  text "MINIMUM PARAMETERS" at 149.584,79.122 h3
  text "HASL" at 39.627,78.203 h3
  text "HASL (PB-FREE)" at 56.127,78.203 h3
  text "GOLDEN FINGER" at 90.377,78.203 h3
  text "F.   IMPEDANCE CONTROL :" at 1.127,75.203 h3
  text "NO" at 39.627,75.203 h3
  text "X  YES  (SEE IMPEDANCE TABLE FOR DETAIL INFORMATION)" at 56.127,75.203 h3
  text "DEFAULT" at 149.584,73.622 h3
  text "G.   THROUGH VIA :" at 1.127,72.203 h3
  text "PLUG THE VIAS WHICH ARE COVERED WITH SOLDERMASK ONE OR TWO SIDE." at 39.627,72.203 h3
  text "PLUG MATERIAL :" at 39.627,69.203 h3
  text "X  SOLDERMASK" at 65.127,69.203 h3
  text "NON-CONDUCTIVE EPOXY." at 90.377,69.203 h3
  text "TRACKS : 0.200mm           / GAPS : 0.120mm" at 149.584,67.872 h3
  text "H.   STACK-UP :" at 1.127,66.203 h3
  text "SEE LAYER STACK-UP SEQUENCE FOR OVERALL THICKNESS." at 39.627,66.203 h3
  text "M.2 Card Edge Bevel" at 46.253,57.991 h1
  text "2 x 20deg. +/- 5 deg." at 49.047,54.864 h1
  text "0.20mm min." at 34.261,49.603 h1
  text "0.80mm +/- 0.08" at 56.867,49.603 h1
  text "Gold finger to Gold finger" at 56.867,48.285 h1
  text "Impedance control is 50 Ohms +/- 5% on all tracks 0.20mm width on top and bottom layers" at 40.883,38.207 h3.5
  text "Symbol" at 43.346,32.767 h2.16
  text "Count" at 51.807,32.767 h2.16
  text "Hole Size" at 60.606,32.767 h2.16
  text "Plated" at 75.25,32.767 h2.16
  text "Hole Type" at 82.678,32.767 h2.16
  text "Drill Layer Pair" at 93.493,32.767 h2.16
  text "Via/Pad" at 113.991,32.767 h2.16
  text "Pad Shape" at 122.853,32.767 h2.16
  text "Template" at 134.429,32.767 h2.16
  text "Description" at 147.145,32.767 h2.16
  text "Hole Tolerance (+)" at 158.771,32.767 h2.16
  text "Hole Tolerance (-)" at 176.85,32.767 h2.16
  text "Hole Length" at 194.443,32.767 h2.16
  text "Routed Path Length" at 206.819,32.767 h2.16
  text "210" at 51.807,29.039 h1.8
  text "7.87mil (0.20mm)" at 60.606,29.039 h1.8
  text "PTH" at 75.25,29.039 h1.8
  text "Round" at 82.678,29.039 h1.8
  text "Top Layer - Bottom Layer" at 93.493,29.039 h1.8
  text "Via" at 113.991,29.039 h1.8
  text "Rounded" at 122.853,29.039 h1.8
  text "v45h20m0mx0" at 134.429,29.039 h1.8
  text "-" at 194.443,29.039 h1.8
  text "-" at 206.819,29.039 h1.8
  text "210 Total" at 51.807,25.311 h1.8
  text ".Layer_Name" at 9,-16.047 h3
  text ".DRL" at 50.695,-16.047 h3
M20-Top Title Box:
  circle w0.254: c87.004,-22.768 r1.3
  region: 86.529,-15.531 71.002,-15.531 70.308,-17.307 69.097,-18.532 67.7,-16.672 67.7,-15.021 68.843,-13.624 70.279,-13.245 86.529,-13.245
  region: 72.526,-23.861 61.77,-23.861 62.763,-21.368 70.621,-21.368 71.07,-20.609 73.278,-23.157
  lines w0.254: 62.763,-21.368 71.555,-21.368 68.489,-17.83 cw(c70.293,-15.886) 70.533,-13.245 87.297,-13.245 86.535,-15.531 ; 66.077,-12.998 cw(c68.503,-13.969) 68.74,-11.366 ; 66.116,-12.966 61.77,-23.861 81.093,-23.861 ccw(c81.341,-21.126) 83.89,-22.146 ; 67.856,-16.9 73.278,-23.157 ; 68.11,-16.9 73.415,-23.022 ; 68.11,-16.646 73.415,-22.768 ; 68.208,-15.531 81.201,-15.531 ; 68.237,-16.519 73.542,-22.641 ; 68.364,-16.392 73.669,-22.514 ; 68.491,-16.265 73.796,-22.387 ; 68.618,-16.138 73.923,-22.26 ; 68.673,-14.186 73.978,-20.307 ; 68.741,-11.366 88.191,-11.366 83.891,-22.144 ; 68.745,-16.011 73.995,-22.07 ; 68.745,-15.757 74.05,-21.879 ; 68.745,-15.503 74.05,-21.625 ; 68.745,-14.614 74.05,-20.736 ; 68.872,-15.376 74.177,-21.498 ; 68.872,-14.995 74.177,-21.117 ; 70.244,-21.381 ccw(c70.349,-20.846) 70.646,-20.389 ; 71.33,-15.518 ccw(c71.304,-16.085) 70.974,-16.547 73.339,-19.276 cw(c71.535,-21.22) 72.268,-23.769 ; 77.611,-23.657 80.501,-15.277 ; 77.834,-23.607 80.703,-15.286 ; 77.961,-23.607 80.83,-15.286 ; 78.215,-23.607 81.084,-15.286 ; 78.469,-23.607 81.338,-15.286 ; 78.723,-23.607 81.592,-15.286 ; 78.977,-23.607 81.846,-15.286 ; 79.231,-23.607 82.1,-15.286 ; 79.485,-23.607 82.354,-15.286 ; 79.739,-23.607 82.608,-15.286 ; 79.947,-23.657 82.837,-15.277 ; 82.837,-15.531 86.529,-15.531 ; 85.861,-15.529 86.623,-13.243 ; 86.027,-15.531 86.789,-13.245 ; 86.281,-15.531 87.043,-13.245
  lines w0.3: 0,-22.747 60,-22.747 ; 0,-17.747 60,-17.747 ; 0,-12.747 60,-12.747 ; 40,-27.747 40,-12.747 ; 60,-27.747 60,-7.747 ; 77.611,-23.657 79.947,-23.657 ; 0,-27.747 0,-7.747 90,-7.747 90,-27.747 0,-27.747
  text "Project: '.Board_Name'" at 1,-10.963 h3
  text "Layer:" at 1,-16.047 h3
  text "Gerber:" at 40.989,-16.047 h3
  text "Variant: '.VariantName'" at 1,-21.047 h3
  text "'.Board_Reference'" at 41.116,-21.047 h3
  text "R" at 86.496,-23.53 h1.52
  text "Date: '.Board_Document_Date'" at 1,-26.047 h3
  text "Rev: '.Board_PCB_Revision'" at 41.059,-26.047 h3
M21-Bottom Title Box:
  circle w0.254: c3.182,-22.768 r1.3
  region: 17.66,-23.861 28.416,-23.861 27.423,-21.368 19.565,-21.368 19.117,-20.609 16.908,-23.157
  region: 3.657,-15.531 19.184,-15.531 19.879,-17.307 21.089,-18.532 22.486,-16.672 22.486,-15.021 21.343,-13.624 19.907,-13.245 3.657,-13.245
  lines w0.254: 3.143,-13.245 3.905,-15.531 ; 3.397,-13.245 4.159,-15.531 ; 3.563,-13.243 4.325,-15.529 ; 3.651,-15.531 2.889,-13.245 19.653,-13.245 cw(c19.894,-15.886) 21.697,-17.83 18.631,-21.368 27.423,-21.368 ; 3.657,-15.531 7.35,-15.531 ; 6.295,-22.144 1.996,-11.366 21.445,-11.366 ; 6.296,-22.146 ccw(c8.845,-21.126) 9.094,-23.861 28.416,-23.861 24.07,-12.966 ; 7.35,-15.277 10.239,-23.657 ; 7.578,-15.286 10.448,-23.607 ; 7.832,-15.286 10.702,-23.607 ; 8.086,-15.286 10.956,-23.607 ; 8.34,-15.286 11.21,-23.607 ; 8.594,-15.286 11.464,-23.607 ; 8.848,-15.286 11.718,-23.607 ; 8.985,-15.531 21.978,-15.531 ; 9.102,-15.286 11.972,-23.607 ; 9.356,-15.286 12.226,-23.607 ; 9.483,-15.286 12.353,-23.607 ; 9.686,-15.277 12.575,-23.657 ; 16.009,-21.498 21.314,-15.376 ; 16.009,-21.117 21.314,-14.995 ; 16.136,-21.879 21.441,-15.757 ; 16.136,-21.625 21.441,-15.503 ; 16.136,-20.736 21.441,-14.614 ; 16.191,-22.07 21.441,-16.011 ; 16.209,-20.307 21.514,-14.186 ; 16.263,-22.26 21.568,-16.138 ; 16.39,-22.387 21.695,-16.265 ; 16.517,-22.514 21.822,-16.392 ; 16.644,-22.641 21.949,-16.519 ; 16.771,-23.022 22.076,-16.9 ; 16.771,-22.768 22.076,-16.646 ; 16.908,-23.157 22.33,-16.9 ; 17.919,-23.769 cw(c18.651,-21.22) 16.848,-19.276 19.212,-16.547 ccw(c18.882,-16.085) 18.856,-15.518 ; 19.54,-20.389 ccw(c19.838,-20.846) 19.943,-21.381 ; 21.447,-11.366 cw(c21.683,-13.969) 24.109,-12.998
  lines w0.3: 10.239,-23.657 12.575,-23.657 ; 30,-27.747 30,-7.747 ; 30,-22.747 90,-22.747 ; 30,-17.747 90,-17.747 ; 30,-12.747 90,-12.747 ; 50,-27.747 50,-12.747 ; 0,-27.747 90,-27.747 90,-7.747 0,-7.747 0,-27.747
  text "Project: '.Board_Name'" at 88.806,-10.963 h3
  text "Gerber:" at 48.817,-16.047 h3
  text "Layer:" at 88.805,-16.047 h3
  text "'.Board_Reference'" at 48.817,-21.047 h3
  text "Variant: '.VariantName'" at 88.806,-21.047 h3
  text "R" at 3.69,-23.53 h1.52
  text "Rev: '.Board_PCB_Revision'" at 48.874,-26.047 h3
  text "Date: '.Board_Document_Date'" at 88.806,-26.047 h3

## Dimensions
48.798,49.573 to 47.673,49.923 on Drill Drawing
52.223,50.873 to 52.298,49.573 on Drill Drawing
47.673,50.473 to 47.698,49.923 on Drill Drawing
13.716,0 to 0.051,-2.159 on M2-Board Dimensions
6.114,44.831 to 26.015,44.831 on M2-Board Dimensions
31.539,-0.044 to 25.964,44.831 on M2-Board Dimensions
32.039,0.456 to 0.039,0.543 on M2-Board Dimensions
